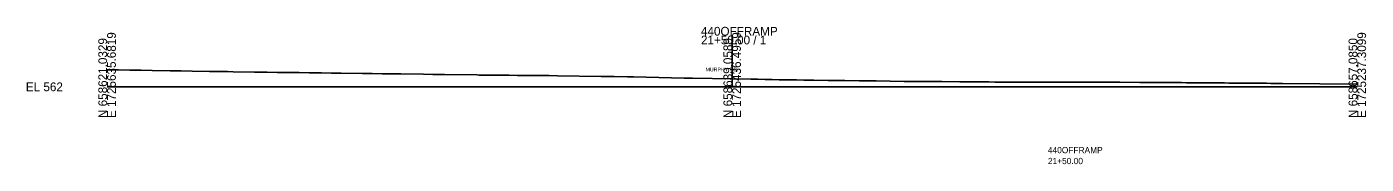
# Model space of a CAD drawing. Extents: x 1728898 to 1729326, y 661368 to 668397.
# Drawn here: x 1728897.8 to 1729326.3, y 668353.3 to 668397.3 of the extents above; entities that cross this region are included whole.
import ezdxf

# ---------------------------------------------------------------- set-up
doc = ezdxf.new("R2010")
doc.units = 0
for name, color, linetype in [('DESIGN - SHEET - Light Grid', 7, 'Continuous'), ('DESIGN - TYPICAL - Text', 7, 'Continuous'), ('DESIGN - TYPICAL - Warning Text', 7, 'Continuous'), ('SURVEY - GROUND - Top of Ground', 7, 'Continuous')]:
    doc.layers.add(name, color=color, linetype=linetype)

msp = doc.modelspace()

# ---------------------------------------------------------------- linework, layer by layer
at = {"layer": 'DESIGN - SHEET - Light Grid'}
for p, q in [((1729123.44, 668378.11), (1729123.44, 668394.5)), ((1728923.44, 668378.11), (1729123.44, 668378.11)), ((1729123.44, 668378.11), (1729323.44, 668378.11))]:
    msp.add_line(p, q, dxfattribs=at)
at = {"layer": 'SURVEY - GROUND - Top of Ground'}
msp.add_lwpolyline([(1728923.44, 668383.57), (1728927.08, 668383.51), (1728930.75, 668383.46), (1728934.35, 668383.4), (1728937.89, 668383.35), (1728943.63, 668383.25), (1728947.19, 668383.2), (1728950.69, 668383.14), (1728956.16, 668383.05), (1728958.15, 668383.02), (1728960.09, 668382.99), (1728961.96, 668382.97), (1728963.79, 668382.94), (1728970.65, 668382.85), (1728971.01, 668382.84), (1728971.32, 668382.83), (1728974.62, 668382.79), (1728977.87, 668382.75), (1728984.88, 668382.65), (1728988.13, 668382.61), (1728991.5, 668382.56), (1728992.07, 668382.55), (1728995.23, 668382.51), (1728998.34, 668382.47), (1729005.19, 668382.39), (1729008.29, 668382.35), (1729011.47, 668382.31), (1729014.48, 668382.27), (1729017.45, 668382.23), (1729024.67, 668382.12), (1729027.62, 668382.08), (1729030.53, 668382.04), (1729030.85, 668382.04), (1729031.37, 668382.03), (1729041.8, 668381.9), (1729042.49, 668381.89), (1729043.15, 668381.88), (1729044.08, 668381.87), (1729044.69, 668381.87), (1729052.04, 668381.81), (1729054.75, 668381.79), (1729062.16, 668381.71), (1729064.83, 668381.69), (1729067.59, 668381.66), (1729081.5, 668381.47), (1729083.46, 668381.44), (1729085.67, 668381.4), (1729089.9, 668381.3), (1729091.86, 668381.26), (1729108.1, 668380.91), (1729109.2, 668380.88), (1729109.88, 668380.87), (1729110.74, 668380.86), (1729123.44, 668380.65), (1729129.35, 668380.55), (1729131.66, 668380.51), (1729133.96, 668380.47), (1729136.26, 668380.43), (1729138.51, 668380.4), (1729144.04, 668380.3), (1729146.39, 668380.27), (1729147.37, 668380.26), (1729149.57, 668380.23), (1729154.09, 668380.16), (1729156.24, 668380.14), (1729156.9, 668380.13), (1729157.39, 668380.12), (1729159.52, 668380.09), (1729164.14, 668380.04), (1729166.24, 668380.01), (1729167.07, 668380.01), (1729167.4, 668380), (1729169.49, 668379.98), (1729178.49, 668379.81), (1729180.06, 668379.79), (1729180.46, 668379.79), (1729182.52, 668379.78), (1729190.47, 668379.77), (1729196.31, 668379.72), (1729198.48, 668379.7), (1729199.63, 668379.69), (1729205.59, 668379.66), (1729207.48, 668379.65), (1729208.97, 668379.64), (1729210.83, 668379.64), (1729215.68, 668379.62), (1729217.72, 668379.61), (1729218.44, 668379.62), (1729220.24, 668379.62), (1729225.93, 668379.6), (1729227.69, 668379.61), (1729229.73, 668379.6), (1729230.08, 668379.6), (1729231.8, 668379.61), (1729236.92, 668379.59), (1729237.4, 668379.59), (1729239.08, 668379.59), (1729245.78, 668379.56), (1729247.42, 668379.56), (1729253.84, 668379.5), (1729257.58, 668379.48), (1729261.24, 668379.46), (1729267.15, 668379.45), (1729268.8, 668379.43), (1729272.87, 668379.42), (1729274.35, 668379.41), (1729277.19, 668379.39), (1729278.06, 668379.38), (1729278.55, 668379.38), (1729279.48, 668379.37), (1729280.92, 668379.35), (1729282.35, 668379.33), (1729290.95, 668379.27), (1729292.33, 668379.25), (1729292.71, 668379.25), (1729293.52, 668379.25), (1729294.37, 668379.23), (1729295.78, 668379.21), (1729297.2, 668379.18), (1729298.6, 668379.16), (1729299.45, 668379.15), (1729323.44, 668379.01)], dxfattribs=at)

# ---------------------------------------------------------------- texts
at = {"layer": 'DESIGN - SHEET - Light Grid'}
for s, p in [('E 1725635.6819', (1728926.24, 668368.11)), ('E 1725436.4959', (1729126.24, 668368.11)), ('E 1725237.3099', (1729326.24, 668368.11)), ('N 658621.0329', (1728923.44, 668368.11)), ('N 658639.0589', (1729123.44, 668368.11)), ('N 658657.0850', (1729323.44, 668368.11))]:
    msp.add_text(s, height=2.8, rotation=90, dxfattribs=at).set_placement(p)
for s, p in [('440OFFRAMP', (1729113.44, 668394.5)), ('21+50.00 / 1', (1729113.44, 668391.7)), ('EL 562', (1728897.44, 668376.71))]:
    msp.add_text(s, height=2.8, dxfattribs=at).set_placement(p)
at = {"layer": 'DESIGN - TYPICAL - Text'}
msp.add_text('MURPHY RD.', height=1.2, rotation=360, dxfattribs=at).set_placement((1729114.94, 668383.05))
at = {"layer": 'DESIGN - TYPICAL - Warning Text'}
for s, p in [('440OFFRAMP', (1729224.44, 668356.86)), ('21+50.00', (1729224.44, 668353.36))]:
    msp.add_text(s, height=2, dxfattribs=at).set_placement(p)

doc.saveas('drawing.dxf')
